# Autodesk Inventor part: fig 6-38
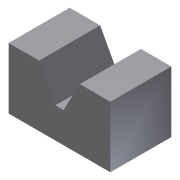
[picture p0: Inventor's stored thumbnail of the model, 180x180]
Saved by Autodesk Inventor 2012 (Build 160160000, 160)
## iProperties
Created: 2005-12
Part Number: fig 6-38
Document SubType Name: Modeling
Designer: CADCIM
Density: 1 g/cm^3
Material: Default
Author: CADCIM
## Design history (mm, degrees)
sketch "Sketch1"
  geometry: L1 (10, 15)-(25, 15); L2 (25, 15)-(25, -15); L3 (25, -15)-(-25, -15); L4 (-25, -15)-(-25, 15); L5 (-25, 15)-(-10, 15); L6 (-10, 15)-(-2, 0); L7 (-2, 0)-(2, 0); L8 (2, 0)-(10, 15); 1 further point
  constraints: 16 end point, 3 equal length, 3 parallel, 1 collinear, 1 horizontal, 1 perpendicular, 1 other
  dimensions: "d0" = 50 distance of L2.end L3.end; "d1" = 25 distance from line of point (0, 0) L2; "d2" = 30 distance of L1.end L2.end; "d3" = 15 distance of L1.start L1.end; "d4" = 15 distance between parallel lines of L1 L7; "d5" = 4 distance of L6.end L7.end; "d6" = 15 distance from line of point (0, 0) L3
extrude "Extrusion1" new body sketch "Sketch1" stored distance "d7" = 30; taper "d8" = 0 deg
body "Solid1"
